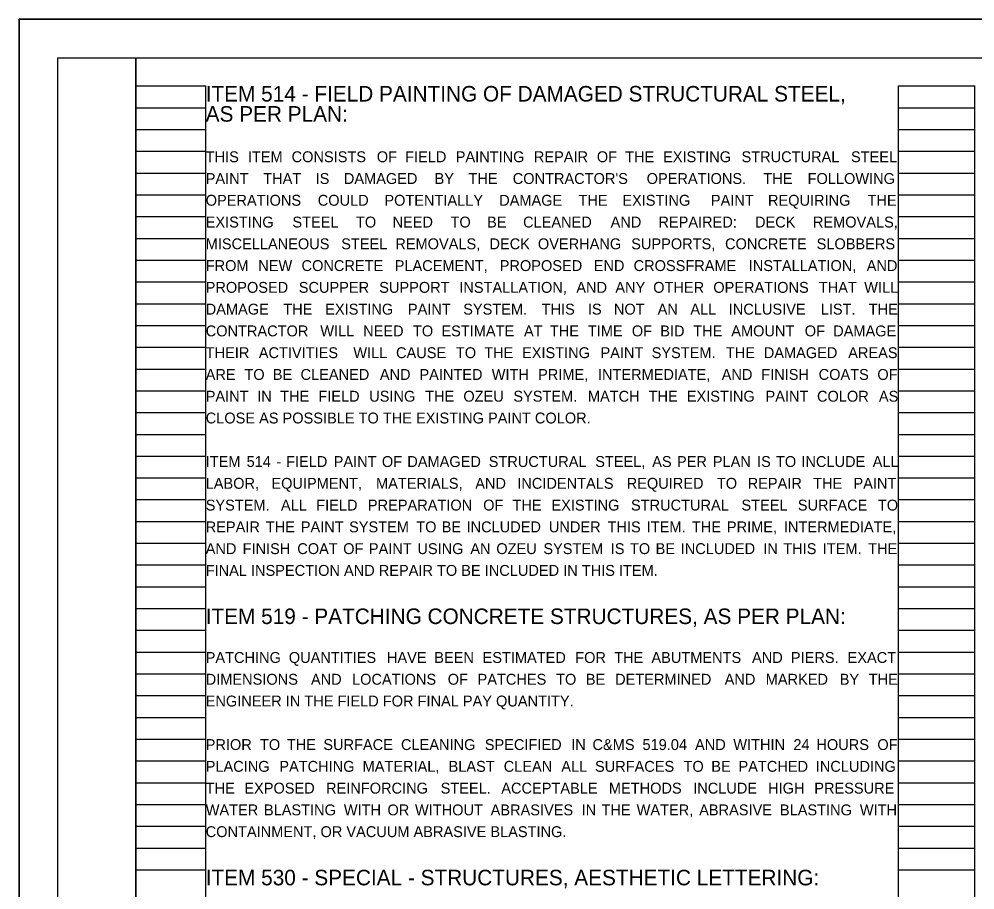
# Model space of a CAD drawing. Extents: x 0 to 34, y 0 to 22.
# Drawn here: x 0 to 12.29, y 10.8 to 22 of the extents above; entities that cross this region are included whole.
import ezdxf

# ---------------------------------------------------------------- set-up
doc = ezdxf.new("R2010")
doc.units = 0
for name, color, linetype in [('BR_P_Gen_Text', 7, 'Continuous'), ('SC_Scratch1', 7, 'Continuous'), ('SH_Border', 7, 'Continuous'), ('SH_Cut_Line', 7, 'Continuous'), ('SH_Text', 7, 'Continuous')]:
    doc.layers.add(name, color=color, linetype=linetype)

msp = doc.modelspace()

# ---------------------------------------------------------------- linework, layer by layer
at = {"layer": 'SC_Scratch1'}
for p, q in [((1.5, 0.98), (1.5, 21.14)), ((1.5, 21.14), (2.4, 21.14)), ((2.4, 0.98), (2.4, 21.14)), ((11.313, 0.98), (11.313, 21.14)), ((11.313, 21.14), (12.293, 21.14)), ((12.293, 0.98), (12.293, 21.14)), ((1.5, 20.86), (2.4, 20.86)), ((11.313, 20.86), (12.293, 20.86)), ((1.5, 20.58), (2.4, 20.58)), ((11.313, 20.58), (12.293, 20.58)), ((1.5, 20.3), (2.4, 20.3)), ((11.313, 20.3), (12.293, 20.3)), ((1.5, 20.02), (2.4, 20.02)), ((11.313, 20.02), (12.293, 20.02)), ((1.5, 19.74), (2.4, 19.74)), ((11.313, 19.74), (12.293, 19.74)), ((1.5, 19.46), (2.4, 19.46)), ((11.313, 19.46), (12.293, 19.46)), ((1.5, 19.18), (2.4, 19.18)), ((11.313, 19.18), (12.293, 19.18)), ((1.5, 18.9), (2.4, 18.9)), ((11.313, 18.9), (12.293, 18.9)), ((1.5, 18.62), (2.4, 18.62)), ((11.313, 18.62), (12.293, 18.62)), ((1.5, 18.34), (2.4, 18.34)), ((11.313, 18.34), (12.293, 18.34)), ((1.5, 18.06), (2.4, 18.06)), ((11.313, 18.06), (12.293, 18.06)), ((1.5, 17.78), (2.4, 17.78)), ((11.313, 17.78), (12.293, 17.78)), ((1.5, 17.5), (2.4, 17.5)), ((11.313, 17.5), (12.293, 17.5)), ((1.5, 17.22), (2.4, 17.22)), ((11.313, 17.22), (12.293, 17.22)), ((1.5, 16.94), (2.4, 16.94)), ((11.313, 16.94), (12.293, 16.94)), ((1.5, 16.66), (2.4, 16.66)), ((11.313, 16.66), (12.293, 16.66)), ((1.5, 16.38), (2.4, 16.38)), ((11.313, 16.38), (12.293, 16.38)), ((1.5, 16.1), (2.4, 16.1)), ((11.313, 16.1), (12.293, 16.1)), ((1.5, 15.82), (2.4, 15.82)), ((11.313, 15.82), (12.293, 15.82)), ((1.5, 15.54), (2.4, 15.54)), ((11.313, 15.54), (12.293, 15.54)), ((1.5, 15.26), (2.4, 15.26)), ((11.313, 15.26), (12.293, 15.26)), ((1.5, 14.98), (2.4, 14.98)), ((11.313, 14.98), (12.293, 14.98)), ((1.5, 14.7), (2.4, 14.7)), ((11.313, 14.7), (12.293, 14.7)), ((1.5, 14.42), (2.4, 14.42)), ((11.313, 14.42), (12.293, 14.42)), ((1.5, 14.14), (2.4, 14.14)), ((11.313, 14.14), (12.293, 14.14)), ((1.5, 13.86), (2.4, 13.86)), ((11.313, 13.86), (12.293, 13.86)), ((1.5, 13.58), (2.4, 13.58)), ((11.313, 13.58), (12.293, 13.58)), ((1.5, 13.3), (2.4, 13.3)), ((11.313, 13.3), (12.293, 13.3)), ((1.5, 13.02), (2.4, 13.02)), ((11.313, 13.02), (12.293, 13.02)), ((1.5, 12.74), (2.4, 12.74)), ((11.313, 12.74), (12.293, 12.74)), ((1.5, 12.46), (2.4, 12.46)), ((11.313, 12.46), (12.293, 12.46)), ((1.5, 12.18), (2.4, 12.18)), ((11.313, 12.18), (12.293, 12.18)), ((1.5, 11.9), (2.4, 11.9)), ((11.313, 11.9), (12.293, 11.9)), ((1.5, 11.62), (2.4, 11.62)), ((11.313, 11.62), (12.293, 11.62)), ((1.5, 11.34), (2.4, 11.34)), ((11.313, 11.34), (12.293, 11.34)), ((1.5, 11.06), (2.4, 11.06)), ((11.313, 11.06), (12.293, 11.06))]:
    msp.add_line(p, q, dxfattribs=at)
msp.add_lwpolyline([(0, 22), (34, 22), (34, 0), (0, 0)], close=True, dxfattribs=at)
at = {"layer": 'SH_Border'}
for points in [[(0.5, 21.5), (1.5, 21.5), (1.5, 0.5), (0.5, 0.5)], [(1.5, 21.5), (33.5, 21.5), (33.5, 0.5), (1.5, 0.5)]]:
    msp.add_lwpolyline(points, close=True, dxfattribs=at)
at = {"layer": 'SH_Cut_Line'}
msp.add_lwpolyline([(0, 0), (34, 0), (34, 22), (0, 22)], close=True, dxfattribs=at)

# ---------------------------------------------------------------- texts
at = {"layer": 'BR_P_Gen_Text'}
for s, p in [('ITEM 514 - FIELD PAINTING OF DAMAGED STRUCTURAL STEEL, ', (2.4, 20.94)), ('AS PER PLAN:', (2.4, 20.681)), ('ITEM 519 - PATCHING CONCRETE STRUCTURES, AS PER PLAN:', (2.4, 14.22)), ('ITEM 530 - SPECIAL - STRUCTURES, AESTHETIC LETTERING:', (2.4, 10.86))]:
    msp.add_text(s, height=0.2, dxfattribs=at).set_placement(p)
at = {"layer": 'SH_Text'}
for s, p in [('THIS ', (2.4, 20.16)), ('ITEM ', (2.942, 20.16)), ('CONSISTS ', (3.505, 20.16)), ('OF ', (4.601, 20.16)), ('FIELD ', (4.965, 20.16)), ('PAINTING ', (5.616, 20.16)), ('REPAIR ', (6.621, 20.16)), ('OF ', (7.431, 20.16)), ('THE ', (7.795, 20.16)), ('EXISTING ', (8.283, 20.16)), ('STRUCTURAL ', (9.292, 20.16)), ('STEEL ', (10.7, 20.16)), ('PAINT ', (2.4, 19.88)), ('THAT ', (3.14, 19.88)), ('IS ', (3.814, 19.88)), ('DAMAGED ', (4.177, 19.88)), ('BY ', (5.344, 19.88)), ('THE ', (5.78, 19.88)), ("CONTRACTOR'S ", (6.349, 19.88)), ('OPERATIONS. ', (8.072, 19.88)), ('THE ', (9.573, 19.88)), ('FOLLOWING ', (10.142, 19.88)), ('OPERATIONS ', (2.4, 19.6)), ('COULD ', (3.841, 19.6)), ('POTENTIALLY ', (4.698, 19.6)), ('DAMAGE ', (6.175, 19.6)), ('THE ', (7.195, 19.6)), ('EXISTING  ', (7.759, 19.6)), ('PAINT ', (8.898, 19.6)), ('REQUIRING ', (9.632, 19.6)), ('THE ', (10.913, 19.6)), ('EXISTING ', (2.4, 19.32)), ('STEEL ', (3.515, 19.32)), ('TO ', (4.333, 19.32)), ('NEED ', (4.803, 19.32)), ('TO ', (5.549, 19.32)), ('BE ', (6.019, 19.32)), ('CLEANED ', (6.482, 19.32)), ('AND ', (7.608, 19.32)), ('REPAIRED: ', (8.223, 19.32)), ('DECK ', (9.465, 19.32)), ('REMOVALS, ', (10.21, 19.32)), ('MISCELLANEOUS ', (2.4, 19.04)), ('STEEL ', (4.143, 19.04)), ('REMOVALS, ', (4.839, 19.04)), ('DECK ', (6.05, 19.04)), ('OVERHANG ', (6.673, 19.04)), ('SUPPORTS, ', (7.873, 19.04)), ('CONCRETE ', (9.08, 19.04)), ('SLOBBERS ', (10.258, 19.04)), ('FROM ', (2.4, 18.76)), ('NEW ', (3.076, 18.76)), ('CONCRETE ', (3.633, 18.76)), ('PLACEMENT, ', (4.831, 18.76)), ('PROPOSED ', (6.182, 18.76)), ('END ', (7.391, 18.76)), ('CROSSFRAME ', (7.904, 18.76)), ('INSTALLATION, ', (9.385, 18.76)), ('AND ', (10.902, 18.76)), ('PROPOSED ', (2.4, 18.48)), ('SCUPPER ', (3.597, 18.48)), ('SUPPORT ', (4.632, 18.48)), ('INSTALLATION, ', (5.662, 18.48)), ('AND ', (7.167, 18.48)), ('ANY ', (7.669, 18.48)), ('OTHER ', (8.156, 18.48)), ('OPERATIONS ', (8.929, 18.48)), ('THAT ', (10.286, 18.48)), ('WILL ', (10.87, 18.48)), ('DAMAGE ', (2.4, 18.2)), ('THE ', (3.398, 18.2)), ('EXISTING ', (3.938, 18.2)), ('PAINT ', (5.001, 18.2)), ('SYSTEM. ', (5.712, 18.2)), ('THIS ', (6.721, 18.2)), ('IS ', (7.316, 18.2)), ('NOT ', (7.65, 18.2)), ('AN ', (8.213, 18.2)), ('ALL ', (8.634, 18.2)), ('INCLUSIVE ', (9.128, 18.2)), ('LIST. ', (10.311, 18.2)), ('THE ', (10.928, 18.2)), ('CONTRACTOR ', (2.4, 17.92)), ('WILL ', (3.874, 17.92)), ('NEED ', (4.425, 17.92)), ('TO ', (5.066, 17.92)), ('ESTIMATE ', (5.432, 17.92)), ('AT ', (6.494, 17.92)), ('THE ', (6.827, 17.92)), ('TIME ', (7.316, 17.92)), ('OF ', (7.881, 17.92)), ('BID ', (8.247, 17.92)), ('THE ', (8.671, 17.92)), ('AMOUNT ', (9.16, 17.92)), ('OF ', (10.105, 17.92)), ('DAMAGE ', (10.471, 17.92)), ('THEIR ', (2.4, 17.64)), ('ACTIVITIES  ', (3.083, 17.64)), ('WILL ', (4.299, 17.64)), ('CAUSE ', (4.848, 17.64)), ('TO ', (5.618, 17.64)), ('THE ', (5.982, 17.64)), ('EXISTING ', (6.469, 17.64)), ('PAINT ', (7.478, 17.64)), ('SYSTEM. ', (8.136, 17.64)), ('THE ', (9.091, 17.64)), ('DAMAGED ', (9.578, 17.64)), ('AREAS ', (10.664, 17.64)), ('ARE ', (2.4, 17.36)), ('TO ', (2.898, 17.36)), ('BE ', (3.263, 17.36)), ('CLEANED ', (3.62, 17.36)), ('AND ', (4.64, 17.36)), ('PAINTED ', (5.149, 17.36)), ('WITH ', (6.079, 17.36)), ('PRIME, ', (6.675, 17.36)), ('INTERMEDIATE, ', (7.445, 17.36)), ('AND ', (9.037, 17.36)), ('FINISH ', (9.546, 17.36)), ('COATS ', (10.284, 17.36)), ('OF ', (11.039, 17.36)), ('PAINT ', (2.4, 17.08)), ('IN ', (3.062, 17.08)), ('THE ', (3.357, 17.08)), ('FIELD ', (3.849, 17.08)), ('USING ', (4.503, 17.08)), ('THE ', (5.222, 17.08)), ('OZEU ', (5.714, 17.08)), ('SYSTEM. ', (6.357, 17.08)), ('MATCH ', (7.316, 17.08)), ('THE ', (8.097, 17.08)), ('EXISTING ', (8.588, 17.08)), ('PAINT ', (9.601, 17.08)), ('COLOR ', (10.263, 17.08)), ('AS ', (11.059, 17.08)), ('CLOSE AS POSSIBLE TO THE EXISTING PAINT COLOR.', (2.4, 16.8)), ('ITEM ', (2.4, 16.24)), ('514 ', (2.926, 16.24)), ('FIELD ', (3.434, 16.24)), ('PAINT ', (4.046, 16.24)), ('OF ', (4.666, 16.24)), ('DAMAGED ', (4.993, 16.24)), ('STRUCTURAL ', (6.04, 16.24)), ('STEEL, ', (7.41, 16.24)), ('AS ', (8.143, 16.24)), ('PER ', (8.462, 16.24)), ('PLAN ', (8.923, 16.24)), ('IS ', (9.492, 16.24)), ('TO ', (9.735, 16.24)), ('INCLUDE ', (10.062, 16.24)), ('ALL ', (10.979, 16.24)), ('- ', (3.31, 16.24)), ('LABOR, ', (2.4, 15.96)), ('EQUIPMENT, ', (3.245, 15.96)), ('MATERIALS, ', (4.591, 15.96)), ('AND ', (5.867, 15.96)), ('INCIDENTALS ', (6.408, 15.96)), ('REQUIRED ', (7.815, 15.96)), ('TO ', (8.975, 15.96)), ('REPAIR ', (9.371, 15.96)), ('THE ', (10.213, 15.96)), ('PAINT ', (10.732, 15.96)), ('SYSTEM. ', (2.4, 15.68)), ('ALL ', (3.368, 15.68)), ('FIELD ', (3.822, 15.68)), ('PREPARATION ', (4.486, 15.68)), ('OF ', (5.969, 15.68)), ('THE ', (6.346, 15.68)), ('EXISTING ', (6.847, 15.68)), ('STRUCTURAL ', (7.87, 15.68)), ('STEEL ', (9.291, 15.68)), ('SURFACE ', (10.016, 15.68)), ('TO ', (11.046, 15.68)), ('REPAIR ', (2.4, 15.4)), ('THE ', (3.173, 15.4)), ('PAINT ', (3.623, 15.4)), ('SYSTEM ', (4.244, 15.4)), ('TO ', (5.108, 15.4)), ('BE ', (5.435, 15.4)), ('INCLUDED ', (5.755, 15.4)), ('UNDER ', (6.814, 15.4)), ('THIS ', (7.569, 15.4)), ('ITEM. ', (8.073, 15.4)), ('THE ', (8.654, 15.4)), ('PRIME, ', (9.104, 15.4)), ('INTERMEDIATE, ', (9.837, 15.4)), ('AND ', (2.4, 15.12)), ('FINISH ', (2.875, 15.12)), ('COAT ', (3.578, 15.12)), ('OF ', (4.169, 15.12)), ('PAINT ', (4.499, 15.12)), ('USING ', (5.123, 15.12)), ('AN ', (5.804, 15.12)), ('OZEU ', (6.138, 15.12)), ('SYSTEM ', (6.743, 15.12)), ('IS ', (7.61, 15.12)), ('TO ', (7.857, 15.12)), ('BE ', (8.187, 15.12)), ('INCLUDED ', (8.51, 15.12)), ('IN ', (9.572, 15.12)), ('THIS ', (9.829, 15.12)), ('ITEM. ', (10.337, 15.12)), ('THE ', (10.92, 15.12)), ('FINAL INSPECTION AND REPAIR TO BE INCLUDED IN THIS ITEM.', (2.4, 14.84)), ('PATCHING ', (2.4, 13.72)), ('QUANTITIES ', (3.469, 13.72)), ('HAVE ', (4.731, 13.72)), ('BEEN ', (5.34, 13.72)), ('ESTIMATED ', (5.961, 13.72)), ('FOR ', (7.153, 13.72)), ('THE ', (7.654, 13.72)), ('ABUTMENTS ', (8.133, 13.72)), ('AND ', (9.427, 13.72)), ('PIERS. ', (9.927, 13.72)), ('EXACT ', (10.656, 13.72)), ('DIMENSIONS ', (2.4, 13.44)), ('AND ', (3.754, 13.44)), ('LOCATIONS ', (4.282, 13.44)), ('OF ', (5.513, 13.44)), ('PATCHES ', (5.897, 13.44)), ('TO ', (6.907, 13.44)), ('BE ', (7.29, 13.44)), ('DETERMINED ', (7.666, 13.44)), ('AND ', (9.075, 13.44)), ('MARKED ', (9.603, 13.44)), ('BY ', (10.555, 13.44)), ('THE ', (10.928, 13.44)), ('ENGINEER IN THE FIELD FOR FINAL PAY QUANTITY.', (2.4, 13.16)), ('PRIOR ', (2.4, 12.6)), ('TO ', (3.098, 12.6)), ('THE ', (3.444, 12.6)), ('SURFACE ', (3.913, 12.6)), ('CLEANING ', (4.912, 12.6)), ('SPECIFIED ', (5.99, 12.6)), ('IN ', (7.101, 12.6)), ('C&MS ', (7.375, 12.6)), ('519.04 ', (8.018, 12.6)), ('AND ', (8.694, 12.6)), ('WITHIN ', (9.186, 12.6)), ('24 ', (9.959, 12.6)), ('HOURS ', (10.255, 12.6)), ('OF ', (11.039, 12.6)), ('PLACING ', (2.4, 12.32)), ('PATCHING ', (3.347, 12.32)), ('MATERIAL, ', (4.418, 12.32)), ('BLAST ', (5.524, 12.32)), ('CLEAN ', (6.233, 12.32)), ('ALL ', (6.974, 12.32)), ('SURFACES ', (7.407, 12.32)), ('TO ', (8.546, 12.32)), ('BE ', (8.903, 12.32)), ('PATCHED ', (9.253, 12.32)), ('INCLUDING ', (10.247, 12.32)), ('THE ', (2.4, 12.04)), ('EXPOSED ', (2.897, 12.04)), ('REINFORCING ', (3.948, 12.04)), ('STEEL. ', (5.422, 12.04)), ('ACCEPTABLE ', (6.202, 12.04)), ('METHODS ', (7.586, 12.04)), ('INCLUDE ', (8.67, 12.04)), ('HIGH ', (9.634, 12.04)), ('PRESSURE ', (10.228, 12.04)), ('WATER ', (2.4, 11.76)), ('BLASTING ', (3.149, 11.76)), ('WITH ', (4.177, 11.76)), ('OR ', (4.738, 11.76)), ('WITHOUT ', (5.092, 11.76)), ('ABRASIVES ', (6.065, 11.76)), ('IN ', (7.235, 11.76)), ('THE ', (7.491, 11.76)), ('WATER, ', (7.943, 11.76)), ('ABRASIVE ', (8.747, 11.76)), ('BLASTING ', (9.786, 11.76)), ('WITH ', (10.814, 11.76)), ('CONTAINMENT, OR VACUUM ABRASIVE BLASTING.', (2.4, 11.48))]:
    msp.add_text(s, height=0.14, dxfattribs=at).set_placement(p)

doc.saveas('drawing.dxf')
